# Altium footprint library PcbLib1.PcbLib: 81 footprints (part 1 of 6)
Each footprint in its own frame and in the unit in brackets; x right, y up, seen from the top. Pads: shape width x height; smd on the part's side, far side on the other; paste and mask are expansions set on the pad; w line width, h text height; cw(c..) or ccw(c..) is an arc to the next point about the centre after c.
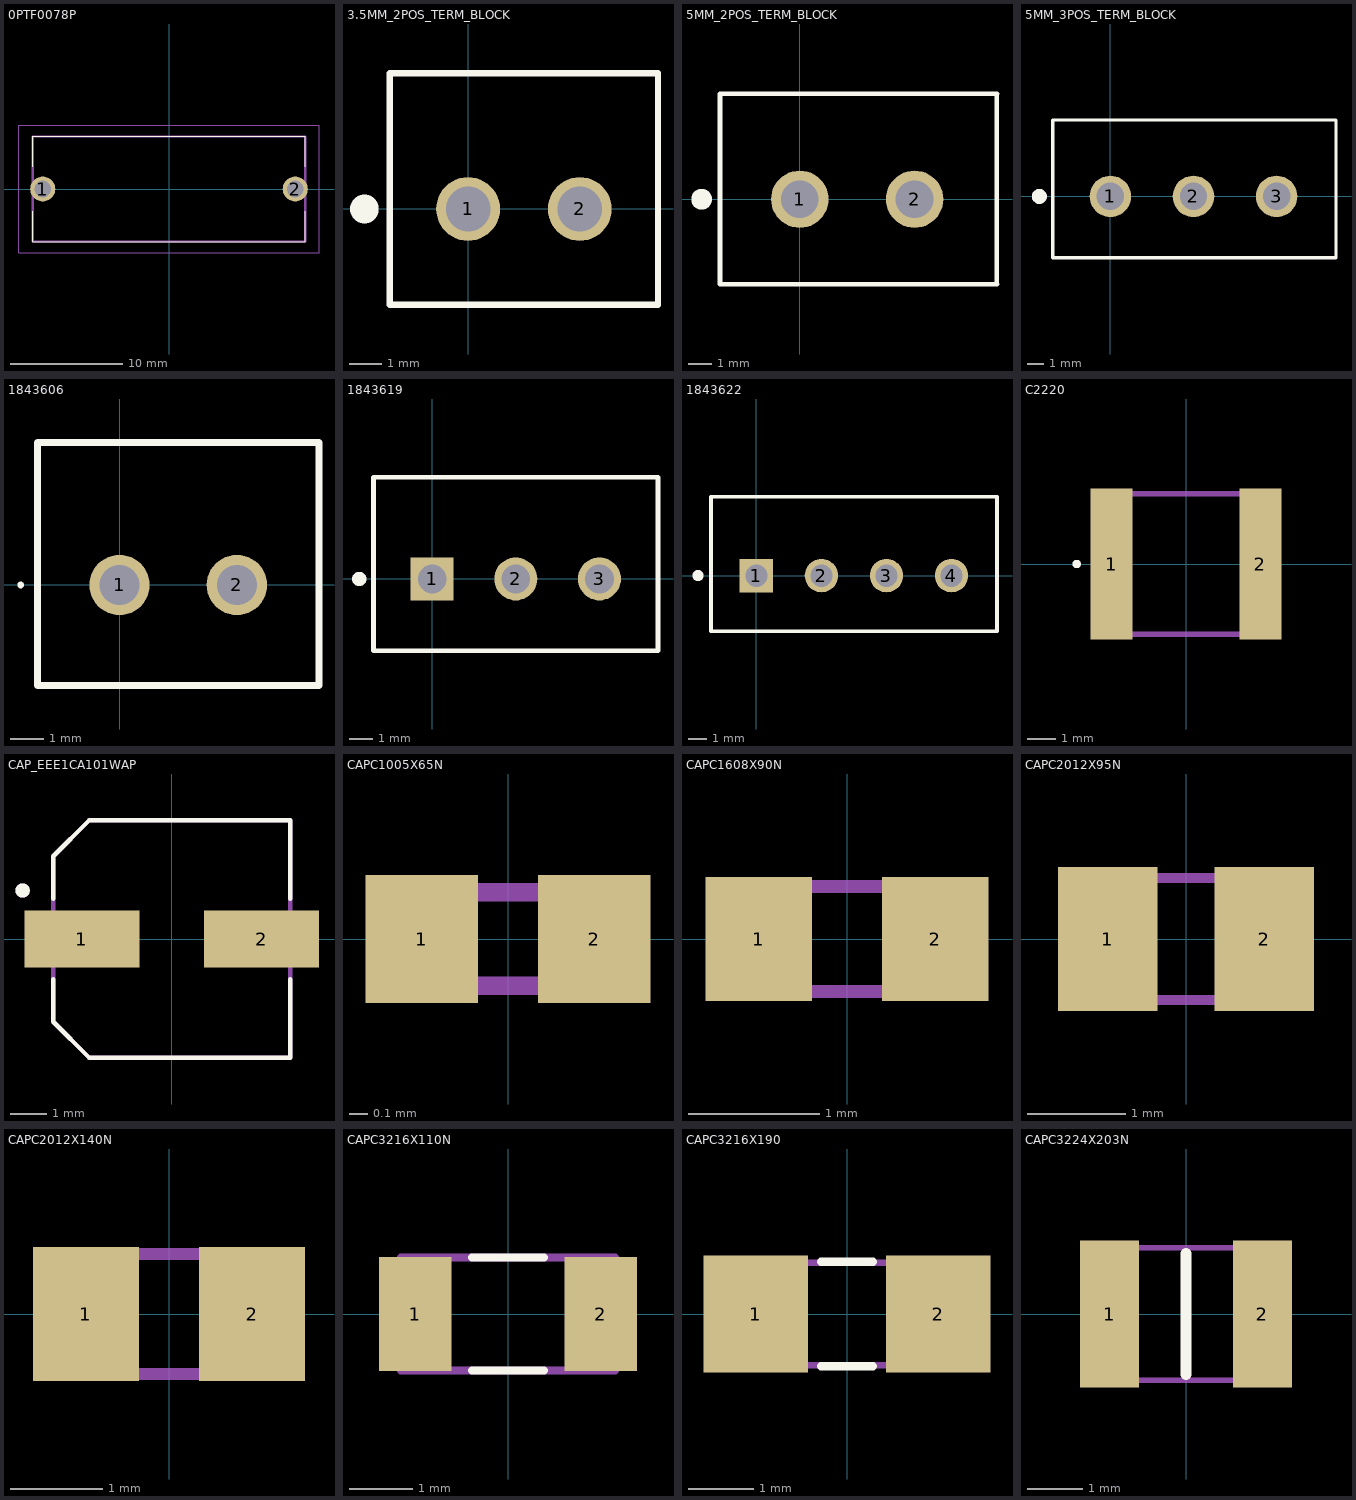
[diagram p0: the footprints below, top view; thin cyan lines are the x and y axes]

## 0PTF0078P [mm]
pads (2):
  round 2.25 hole 1.5: 1(-11.3,0) 2(11.3,0)
Top Overlay:
  lines w0.1: -12.2,-2 -12.2,-4.7 12.2,-4.7 12.2,-2 ; -12.2,2 -12.2,4.7 12.2,4.7 12.2,2
Mechanical 13:
  lines w0.2: -12.2,-4.7 12.2,-4.7 12.2,4.7 -12.2,4.7 -12.2,-4.7
Mechanical 15:
  lines w0.1: -13.425,-5.7 13.425,-5.7 13.425,5.7 -13.425,5.7 -13.425,-5.7
3D body "0PTF0078P.stp": height 11.45, standoff -3.55, extent -12.2,-4.7 12.2,4.7
3D body "0218010.HXP.stp": height 10.1, standoff 4.9, extent -10,-2.6 10,2.6

## 3.5MM_2POS_TERM_BLOCK [mm]
pads (2):
  round 2 hole 1.4: 1(0,0) 2(3.5,0)
Top Overlay:
  lines w0.2: -2.45,-3 -2.45,4.25 5.95,4.25 5.95,-3 -2.45,-3
  lines w0.5: -3.45,0 cw(c-3.25,0) -3.05,0 cw(c-3.25,0) -3.45,0
Mechanical 13:
  lines w0.1: -2.45,-3 -2.45,4.25 5.95,4.25 5.95,-3 -2.45,-3
3D body "1843606.stp": height 9.2, standoff -3.4, extent -2.45,-2.99 5.95,4.26

## 5MM_2POS_TERM_BLOCK [mm]
pads (2):
  round 2.5 hole 1.65: 1(0,0) 2(5,0)
Top Overlay:
  lines w0.2: 8.575,-3.7 8.575,4.6 ; 8.585,-3.7 -3.475,-3.7 -3.475,4.6 8.585,4.6
  lines w0.5: -4.475,0 cw(c-4.275,0) -4.075,0 cw(c-4.275,0) -4.475,0
Mechanical 13:
  lines w0.1: -3.475,-3.71 -3.475,4.6 8.575,4.6 8.575,-3.71 -3.475,-3.71
3D body "1836299.stp": height 9.68, standoff -2.92, extent -2.54,-2.9 7.62,4.35

## 5MM_3POS_TERM_BLOCK [mm]
pads (3):
  round 2.5 hole 1.65: 1(0,0) 2(5,0) 3(10,0)
Top Overlay:
  lines w0.2: -3.475,-3.7 -3.475,4.6 13.575,4.6 13.575,-3.7 -3.475,-3.7
  lines w0.5: -4.475,0 cw(c-4.275,0) -4.075,0 cw(c-4.275,0) -4.475,0
Mechanical 13:
  lines w0.1: 8.575,4.6 -3.475,4.6 -3.475,-3.71 13.575,-3.71 13.575,4.6
3D body "1836299.stp": height 9.68, standoff -2.92, extent -2.54,-2.9 7.62,4.35
3D body "1836299.stp": height 9.68, standoff -2.92, extent 2.46,-2.9 12.62,4.35

## 1843606 [mm]
pads (2):
  round 1.8 hole 1.2: 1(0,0) 2(3.5,0)
Top Overlay:
  lines w0.1: -3,0 ccw(c-2.95,0) -2.9,0 ccw(c-2.95,0) -3,0
  lines w0.2: -2.45,-3 5.95,-3 5.95,4.25 -2.45,4.25 -2.45,-3
Mechanical 13:
  lines w0.1: -2.45,-3 5.95,-3 5.95,4.25 -2.45,4.25 -2.45,-3
3D body "1843606.stp": height 9.2, standoff -3.4, extent -2.45,-2.99 5.95,4.26

## 1843619 [mm]
pads (3):
  rect 1.8x1.8 hole 1.2: 1(0,0)
  round 1.8 hole 1.2: 2(3.5,0) 3(7,0)
Top Overlay:
  lines w0.2: -2.45,-3 9.45,-3 9.45,4.25 -2.45,4.25 -2.45,-3
  lines w0.5: -3.1,0 ccw(c-3.05,0) -3,0 ccw(c-3.05,0) -3.1,0
Mechanical 13:
  lines w0.1: -2.45,-3 9.45,-3 9.45,4.25 -2.45,4.25 -2.45,-3
3D body "1843619.stp": height 9.2, standoff -3.4, extent -2.45,-2.95 9.45,4.61

## 1843622 [mm]
pads (4):
  rect 1.8x1.8 hole 1.2: 1(0,0)
  round 1.8 hole 1.2: 2(3.5,0) 3(7,0) 4(10.5,0)
Top Overlay:
  lines w0.2: -2.45,-3 12.95,-3 12.95,4.25 -2.45,4.25 -2.45,-3
  lines w0.5: -3.2,0 ccw(c-3.15,0) -3.1,0 ccw(c-3.15,0) -3.2,0
Mechanical 13:
  lines w0.1: -2.45,-3 12.95,-3 12.95,4.25 -2.45,4.25 -2.45,-3
3D body "1843622.stp": height 9.88, standoff -2.72, extent -2.45,-3.125 12.95,4.375

## C2220 [mm]
pads (2):
  rect 1.5x5.4 smd: 1(-2.65,0) 2(2.65,0)
Top Overlay:
  circle w0.2: c-3.9,0 r0.05
Mechanical 13:
  lines w0.2: -2.85,-2.5 2.85,-2.5 2.85,2.5 -2.85,2.5 -2.85,-2.5
3D body "C2220C474K5RACAUTO.stp": height 1.14, standoff -0.01, extent -3,-2.7 3.1,2.7

## CAP_EEE1CA101WAP [mm]
pads (2):
  rect 3.2x1.6 smd: 1(-2.5,0) 2(2.5,0)
Top Overlay:
  circle w0.2: c-4.15,1.35 r0.1
  lines w0.127: -3.3,-1.12 -3.3,-2.3 -2.3,-3.3 3.3,-3.3 3.3,-1.12 ; -3.3,1.12 -3.3,2.3 -2.3,3.3 3.3,3.3 3.3,1.12
Mechanical 13:
  circle w0.2: c-4.15,1.35 r0.1
  lines w0.127: -3.3,-2.3 -3.3,2.3 -2.3,3.3 3.3,3.3 3.3,-3.3 -2.3,-3.3 -3.3,-2.3
3D body "step_temp.STEP": height 5.8, standoff 0, extent -3.65,-3.3 3.65,3.3

## CAPC1005X65N [mm] "0402"
pads (2):
  rect 0.6x0.68 smd: 1(-0.46,0) 2(0.46,0)
Mechanical 13:
  lines w0.1: -0.5,-0.25 -0.5,0.25 0.5,0.25 0.5,-0.25 -0.5,-0.25
3D body "CL05A105KL5NRNC.stp": height 0.65, standoff 0, extent -0.5,-0.25 0.5,0.25

## CAPC1608X90N [mm] "0603"
pads (2):
  rect 0.81x0.94 smd: 1(-0.67,0) 2(0.67,0)
Mechanical 13:
  lines w0.1: -0.8,-0.4 0.8,-0.4 0.8,0.4 -0.8,0.4 -0.8,-0.4
3D body "EMK107B7105KA-T.stp": height 0.9, standoff 0, extent -0.8,-0.4 0.8,0.4

## CAPC2012X95N [mm] "0805"
pads (2):
  rect 1.02x1.47 smd: 1(-0.8,0) 2(0.8,0)
Mechanical 13:
  lines w0.1: -1,-0.625 -1,0.625 1,0.625 1,-0.625 -1,-0.625
3D body "CC0805KRX7R8BB104.stp": height 0.95, standoff 0, extent -1,-0.625 1,0.625

## CAPC2012X140N [mm]
pads (2):
  rect 1.15x1.45 smd: 1(-0.9,0) 2(0.9,0)
Mechanical 13:
  lines w0.127: -1,-0.65 -1,0.65 1,0.65 1,-0.65 -1,-0.65
3D body "step_temp.STEP": height 0.94, standoff 0, extent -1.005,-0.625 1.005,0.625

## CAPC3216X110N [mm]
pads (2):
  rect 1.16x1.82 smd: 1(-1.475,0) 2(1.475,0)
Top Overlay:
  lines w0.127: -0.57,-0.9 0.57,-0.9 ; -0.57,0.9 0.57,0.9
Mechanical 13:
  lines w0.127: -1.7,-0.9 1.7,-0.9 1.7,0.9 -1.7,0.9 -1.7,-0.9
3D body "step_temp.STEP": height 0.85, standoff 0, extent -1.6,-0.8 1.6,0.8

## CAPC3216X190 [mm]
pads (2):
  rect 1.6x1.8 smd: 1(-1.4,0) 2(1.4,0)
Top Overlay:
  lines w0.127: -0.4,-0.8 0.4,-0.8 ; -0.4,0.8 0.4,0.8
Mechanical 13:
  region: -0.952,-0.851 -1.702,-0.851 -1.702,0.849 -0.952,0.849
  region: 1.702,-0.849 0.952,-0.849 0.952,0.851 1.702,0.851
  lines w0.102: -0.965,-0.787 0.965,-0.787 ; -0.965,0.787 0.965,0.787
3D body "step_temp.STEP": height 1.5, standoff 0, extent -1.6,-0.8 1.6,0.8

## CAPC3224X203N [mm]
pads (2):
  rect 1.07x2.68 smd: 1(-1.39,0) 2(1.39,0)
Top Overlay:
  lines w0.2: 0,-1.105 0,1.105
Mechanical 13:
  lines w0.1: -1.59,-1.205 -1.59,1.205 1.59,1.205 1.59,-1.205 -1.59,-1.205
3D body "202S41W472KV4E.stp": height 2.03, standoff 0, extent -1.59,-1.205 1.59,1.205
